(* Logix 5000 project; controller Test vendor 1 type 14 code 92 rev 33.11; software revision 33.00; part 2 of 2 *)

ADD_ON_INSTRUCTION Banner_CL50Pro_PD_v4   (* revision 4.0, vendor Banner Engineering *)
// Takes the raw SINT information and converts that data into actual information.
VAR_IN_OUT
   Process_Data : Banner_CL50Pro_PDO_v4; {required}
END_VAR
VAR_INPUT
   Byte_Swap : BOOL; {required}
END_VAR
VAR
   PDO_Temp : SINT[10]; {access None}
   PDI_Temp : SINT[2]; {access None}
END_VAR

ROUTINE Logic   (* ladder *)
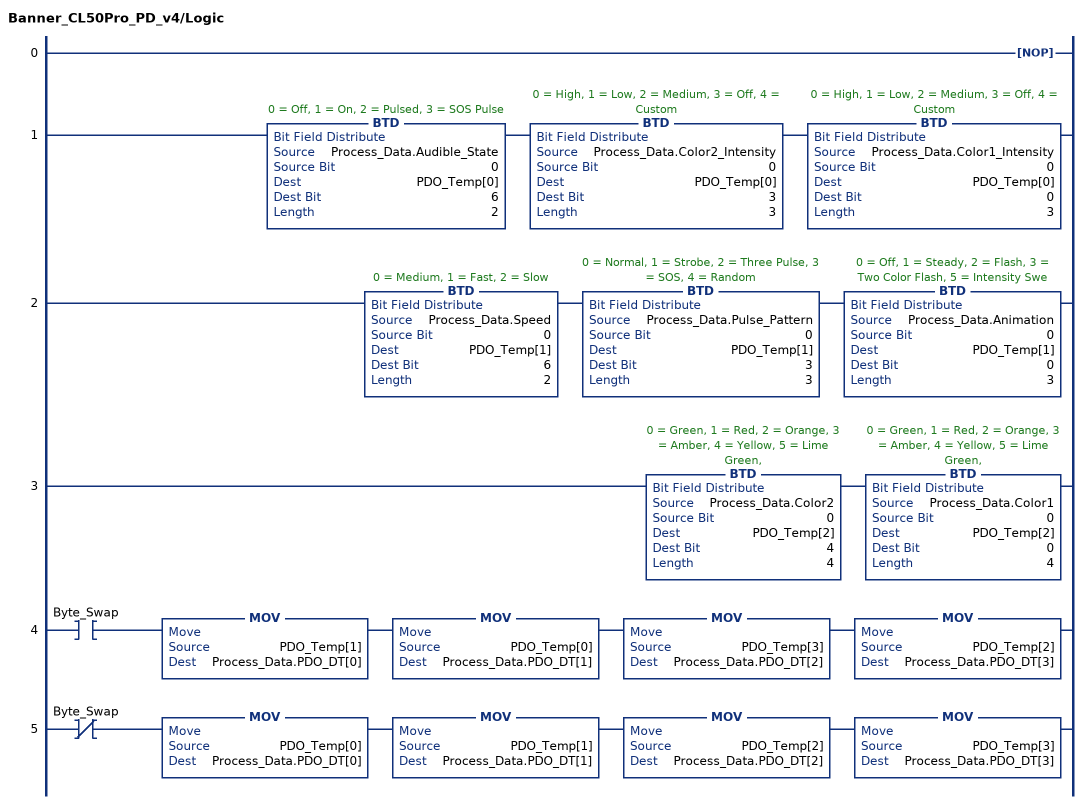
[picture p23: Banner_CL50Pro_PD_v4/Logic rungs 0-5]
   0: NOP();
   1: BTD(Process_Data.Audible_State,0,PDO_Temp[0],6,2)BTD(Process_Data.Color2_Intensity,0,PDO_Temp[0],3,3)BTD(Process_Data.Color1_Intensity,0,PDO_Temp[0],0,3);
   2: BTD(Process_Data.Speed,0,PDO_Temp[1],6,2)BTD(Process_Data.Pulse_Pattern,0,PDO_Temp[1],3,3)BTD(Process_Data.Animation,0,PDO_Temp[1],0,3);
   3: BTD(Process_Data.Color2,0,PDO_Temp[2],4,4)BTD(Process_Data.Color1,0,PDO_Temp[2],0,4);
   4: XIC(Byte_Swap)MOV(PDO_Temp[1],Process_Data.PDO_DT[0])MOV(PDO_Temp[0],Process_Data.PDO_DT[1])MOV(PDO_Temp[3],Process_Data.PDO_DT[2])MOV(PDO_Temp[2],Process_Data.PDO_DT[3]);
   5: XIO(Byte_Swap)MOV(PDO_Temp[0],Process_Data.PDO_DT[0])MOV(PDO_Temp[1],Process_Data.PDO_DT[1])MOV(PDO_Temp[2],Process_Data.PDO_DT[2])MOV(PDO_Temp[3],Process_Data.PDO_DT[3]);
END_ROUTINE
END_ADD_ON_INSTRUCTION

ADD_ON_INSTRUCTION Banner_DXMR90_IOLM_v4   (* revision 4.1, vendor Banner Engineering *)
// AOI that controls a Banner IO-Link Master with Banner devices.
// Revision note:
// Revised operational order for ISDU write.
VAR_IN_OUT
   IOLM : Banner_IOLM_v4; {required}
END_VAR
VAR
   Lock : DINT; {access None}
   Byte_Length : SINT; {access None}
   Current_Port : INT; {access None}   // Current port to communicate with via the IO-Link Master.
   Timer : TIMER := (PRE := 500); {access None}
   Error_Index : DINT; {access None}
   Timer2 : TIMER := (PRE := 5000); {access None}
   Temp_Index : INT; {access None}
   ErrCount : DINT; {access None}
   Timer4 : TIMER := (PRE := 2000); {access None}
   Timer5 : TIMER := (PRE := 2000); {access None}
   Timer3 : TIMER := (PRE := 2000); {access None}
   Timer6 : TIMER := (PRE := 3000); {access None}
   Timer7 : TIMER := (PRE := 3000); {access None}
END_VAR

ROUTINE Logic   (* ladder *)
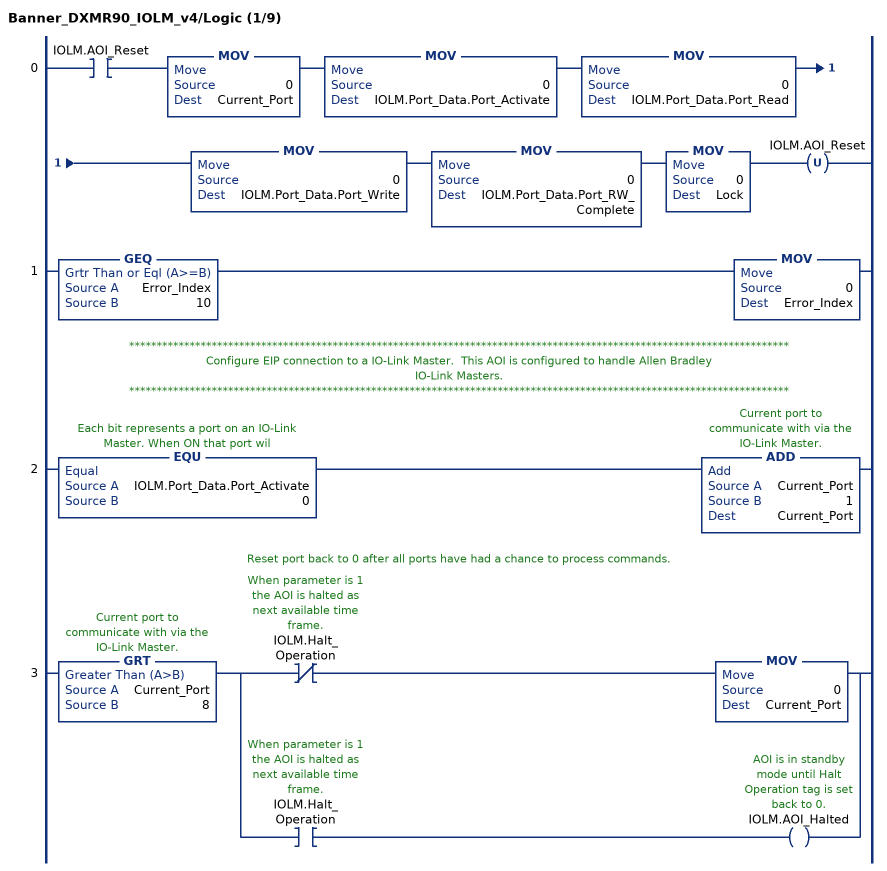
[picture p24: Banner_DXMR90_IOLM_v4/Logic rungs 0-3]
   0: XIC(IOLM.AOI_Reset)MOV(0,Current_Port)MOV(0,IOLM.Port_Data.Port_Activate)MOV(0,IOLM.Port_Data.Port_Read)MOV(0,IOLM.Port_Data.Port_Write)MOV(0,IOLM.Port_Data.Port_RW_Complete)MOV(0,Lock)OTU(IOLM.AOI_Reset);
   1: GEQ(Error_Index,10)MOV(0,Error_Index);
   // ************************************************************************************************************************
   // Configure EIP connection to a IO-Link Master.  This AOI is configured to handle Allen Bradley
   // IO-Link Masters.
   // ************************************************************************************************************************
   2: EQU(IOLM.Port_Data.Port_Activate,0)ADD(Current_Port,1,Current_Port);
   // Reset port back to 0 after all ports have had a chance to process commands.
   3: GRT(Current_Port,8)[XIO(IOLM.Halt_Operation) MOV(0,Current_Port) ,XIC(IOLM.Halt_Operation) OTE(IOLM.AOI_Halted) ];
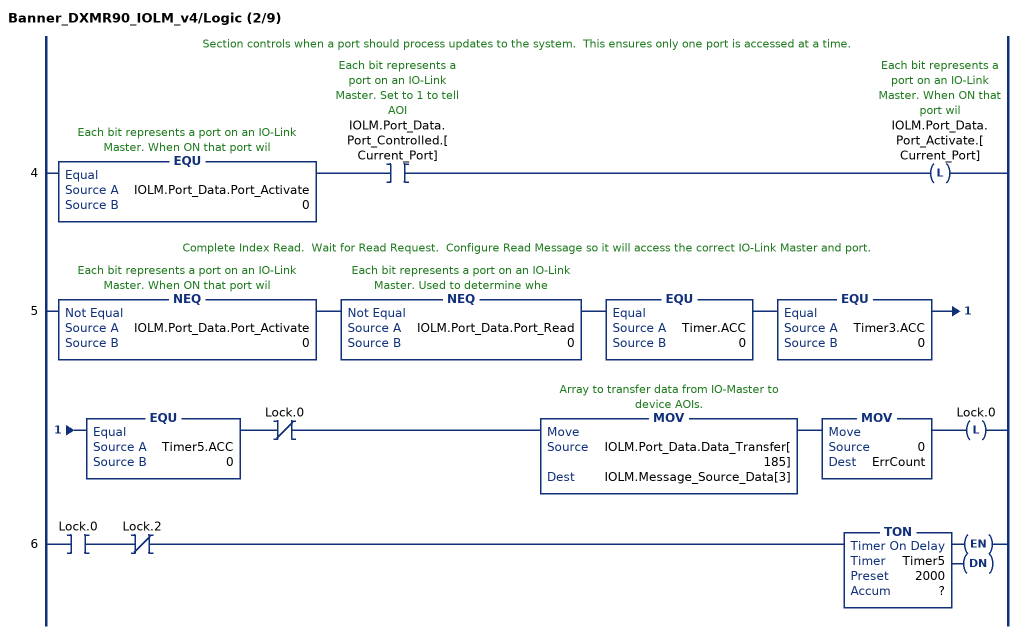
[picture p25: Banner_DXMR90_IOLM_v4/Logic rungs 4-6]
   // Section controls when a port should process updates to the system.  This ensures only one port is accessed at a time.
   4: EQU(IOLM.Port_Data.Port_Activate,0)XIC(IOLM.Port_Data.Port_Controlled.[Current_Port])OTL(IOLM.Port_Data.Port_Activate.[Current_Port]);
   // Complete Index Read.  Wait for Read Request.  Configure Read Message so it will access the correct IO-Link Master and port.
   5: NEQ(IOLM.Port_Data.Port_Activate,0)NEQ(IOLM.Port_Data.Port_Read,0)EQU(Timer.ACC,0)EQU(Timer3.ACC,0)EQU(Timer5.ACC,0)XIO(Lock.0)MOV(IOLM.Port_Data.Data_Transfer[185],IOLM.Message_Source_Data[3])MOV(0,ErrCount)OTL(Lock.0);
   6: XIC(Lock.0)XIO(Lock.2)TON(Timer5,?,?);
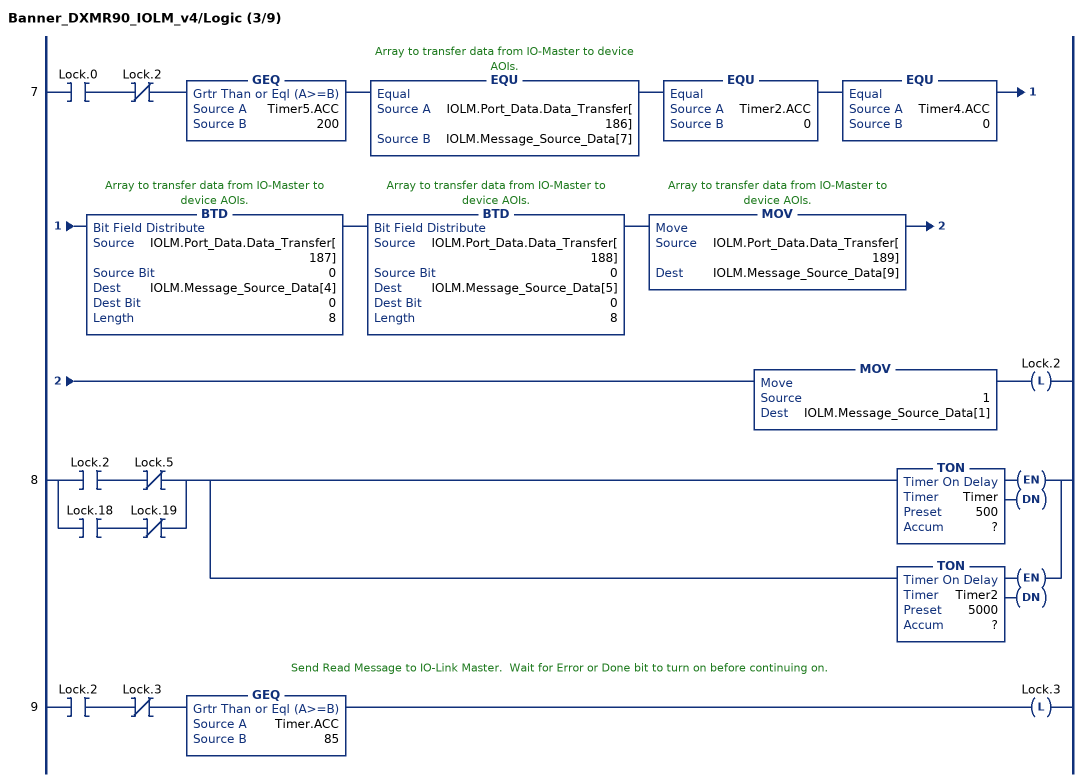
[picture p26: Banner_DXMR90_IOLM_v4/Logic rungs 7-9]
   7: XIC(Lock.0)XIO(Lock.2)GEQ(Timer5.ACC,200)EQU(IOLM.Port_Data.Data_Transfer[186],IOLM.Message_Source_Data[7])EQU(Timer2.ACC,0)EQU(Timer4.ACC,0)BTD(IOLM.Port_Data.Data_Transfer[187],0,IOLM.Message_Source_Data[4],0,8)BTD(IOLM.Port_Data.Data_Transfer[188],0,IOLM.Message_Source_Data[5],0,8)MOV(IOLM.Port_Data.Data_Transfer[189],IOLM.Message_Source_Data[9])MOV(1,IOLM.Message_Source_Data[1])OTL(Lock.2);
   8: [XIC(Lock.2) XIO(Lock.5) ,XIC(Lock.18) XIO(Lock.19) ][TON(Timer,?,?) ,TON(Timer2,?,?) ];
   // Send Read Message to IO-Link Master.  Wait for Error or Done bit to turn on before continuing on.
   9: XIC(Lock.2)XIO(Lock.3)GEQ(Timer.ACC,85)OTL(Lock.3);
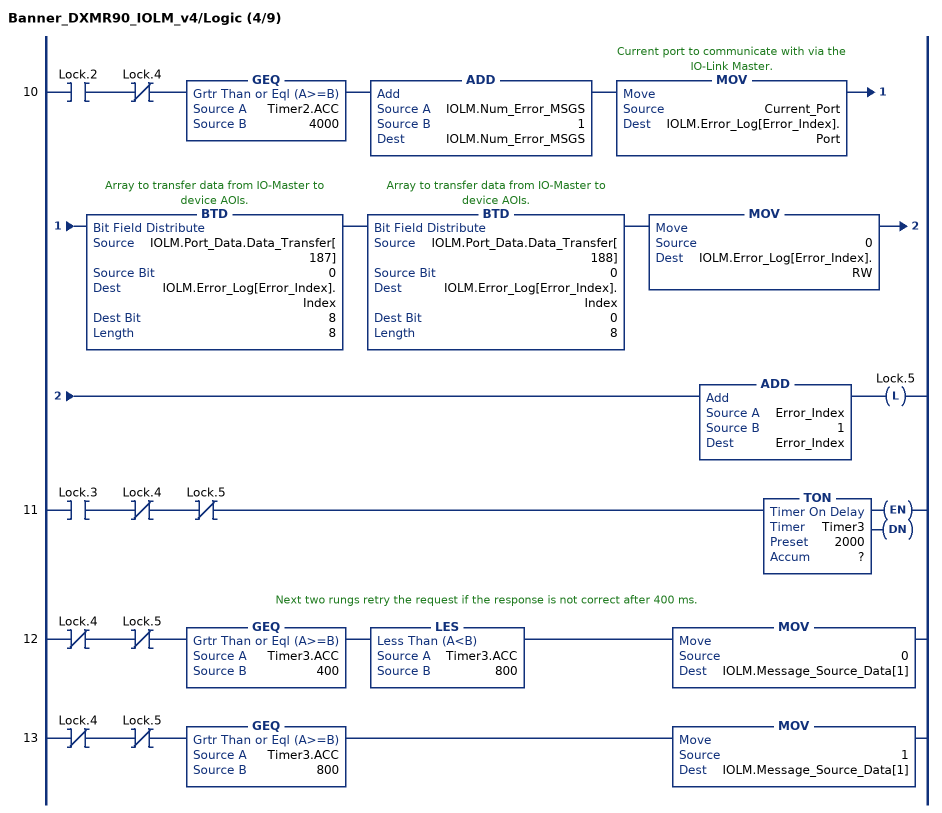
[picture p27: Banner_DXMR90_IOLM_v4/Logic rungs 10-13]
   10: XIC(Lock.2)XIO(Lock.4)GEQ(Timer2.ACC,4000)ADD(IOLM.Num_Error_MSGS,1,IOLM.Num_Error_MSGS)MOV(Current_Port,IOLM.Error_Log[Error_Index].Port)BTD(IOLM.Port_Data.Data_Transfer[187],0,IOLM.Error_Log[Error_Index].Index,8,8)BTD(IOLM.Port_Data.Data_Transfer[188],0,IOLM.Error_Log[Error_Index].Index,0,8)MOV(0,IOLM.Error_Log[Error_Index].RW)ADD(Error_Index,1,Error_Index)OTL(Lock.5);
   11: XIC(Lock.3)XIO(Lock.4)XIO(Lock.5)TON(Timer3,?,?);
   // Next two rungs retry the request if the response is not correct after 400 ms.
   12: XIO(Lock.4)XIO(Lock.5)GEQ(Timer3.ACC,400)LES(Timer3.ACC,800)MOV(0,IOLM.Message_Source_Data[1]);
   13: XIO(Lock.4)XIO(Lock.5)GEQ(Timer3.ACC,800)MOV(1,IOLM.Message_Source_Data[1]);
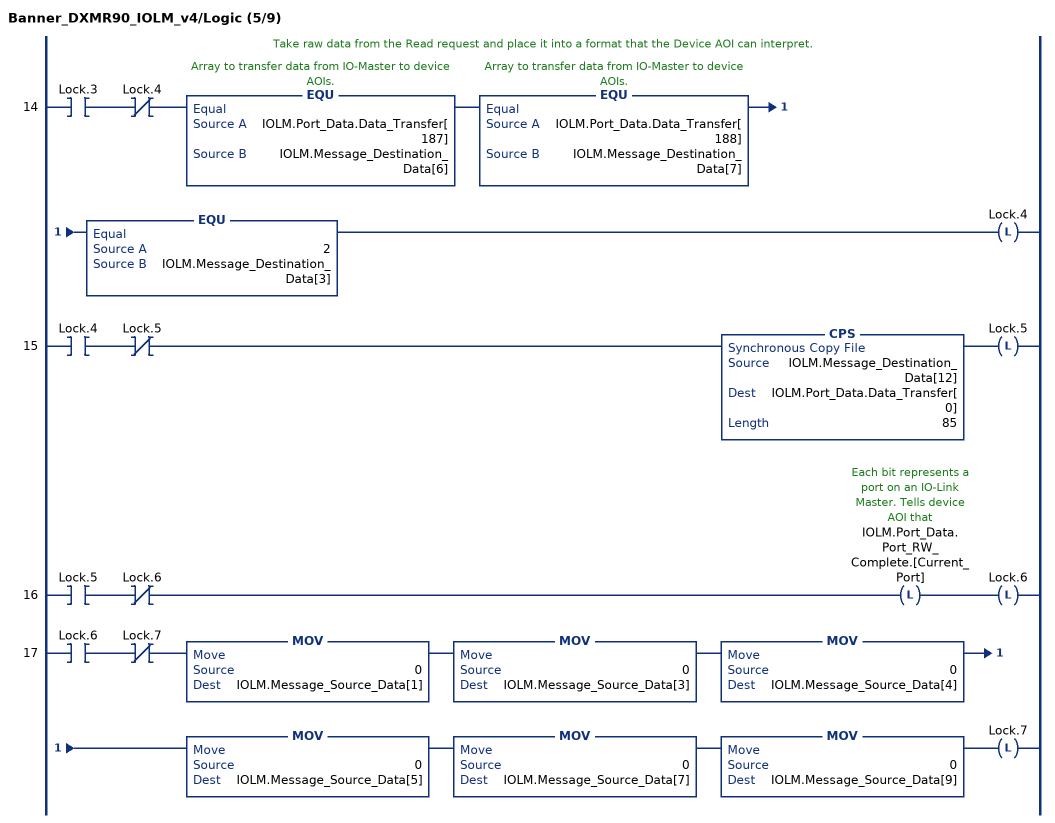
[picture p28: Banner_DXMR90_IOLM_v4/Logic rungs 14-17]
   // Take raw data from the Read request and place it into a format that the Device AOI can interpret.
   14: XIC(Lock.3)XIO(Lock.4)EQU(IOLM.Port_Data.Data_Transfer[187],IOLM.Message_Destination_Data[6])EQU(IOLM.Port_Data.Data_Transfer[188],IOLM.Message_Destination_Data[7])EQU(2,IOLM.Message_Destination_Data[3])OTL(Lock.4);
   15: XIC(Lock.4)XIO(Lock.5)CPS(IOLM.Message_Destination_Data[12],IOLM.Port_Data.Data_Transfer[0],85)OTL(Lock.5);
   16: XIC(Lock.5)XIO(Lock.6)OTL(IOLM.Port_Data.Port_RW_Complete.[Current_Port])OTL(Lock.6);
   17: XIC(Lock.6)XIO(Lock.7)MOV(0,IOLM.Message_Source_Data[1])MOV(0,IOLM.Message_Source_Data[3])MOV(0,IOLM.Message_Source_Data[4])MOV(0,IOLM.Message_Source_Data[5])MOV(0,IOLM.Message_Source_Data[7])MOV(0,IOLM.Message_Source_Data[9])OTL(Lock.7);
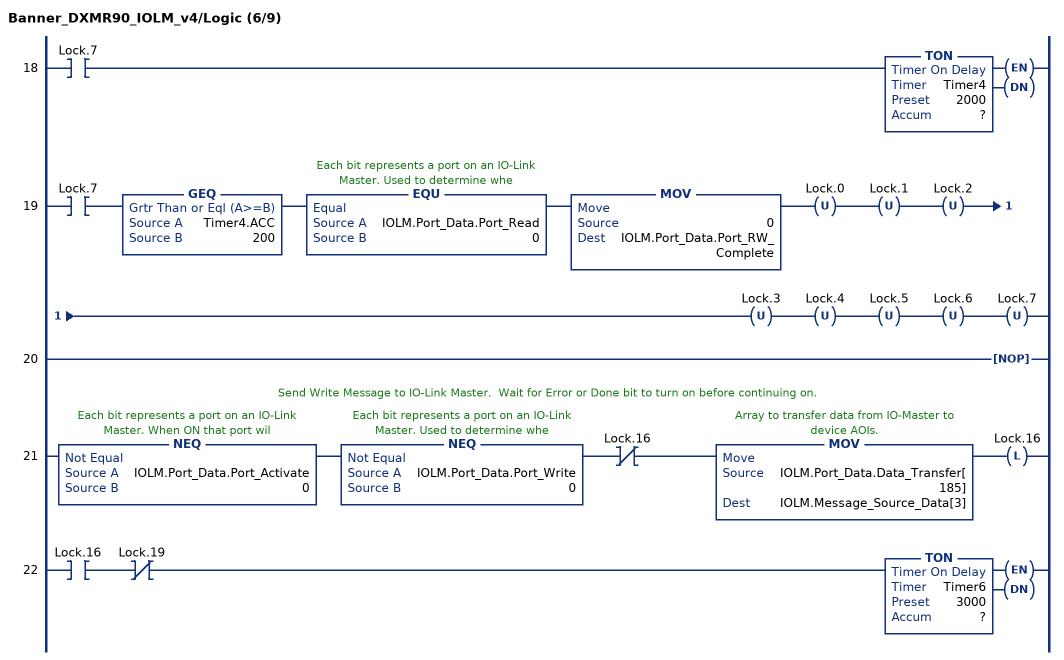
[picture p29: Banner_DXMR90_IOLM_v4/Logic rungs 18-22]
   18: XIC(Lock.7)TON(Timer4,?,?);
   19: XIC(Lock.7)GEQ(Timer4.ACC,200)EQU(IOLM.Port_Data.Port_Read,0)MOV(0,IOLM.Port_Data.Port_RW_Complete)OTU(Lock.0)OTU(Lock.1)OTU(Lock.2)OTU(Lock.3)OTU(Lock.4)OTU(Lock.5)OTU(Lock.6)OTU(Lock.7);
   20: NOP();
   // Send Write Message to IO-Link Master.  Wait for Error or Done bit to turn on before continuing on.
   21: NEQ(IOLM.Port_Data.Port_Activate,0)NEQ(IOLM.Port_Data.Port_Write,0)XIO(Lock.16)MOV(IOLM.Port_Data.Data_Transfer[185],IOLM.Message_Source_Data[3])OTL(Lock.16);
   22: XIC(Lock.16)XIO(Lock.19)TON(Timer6,?,?);
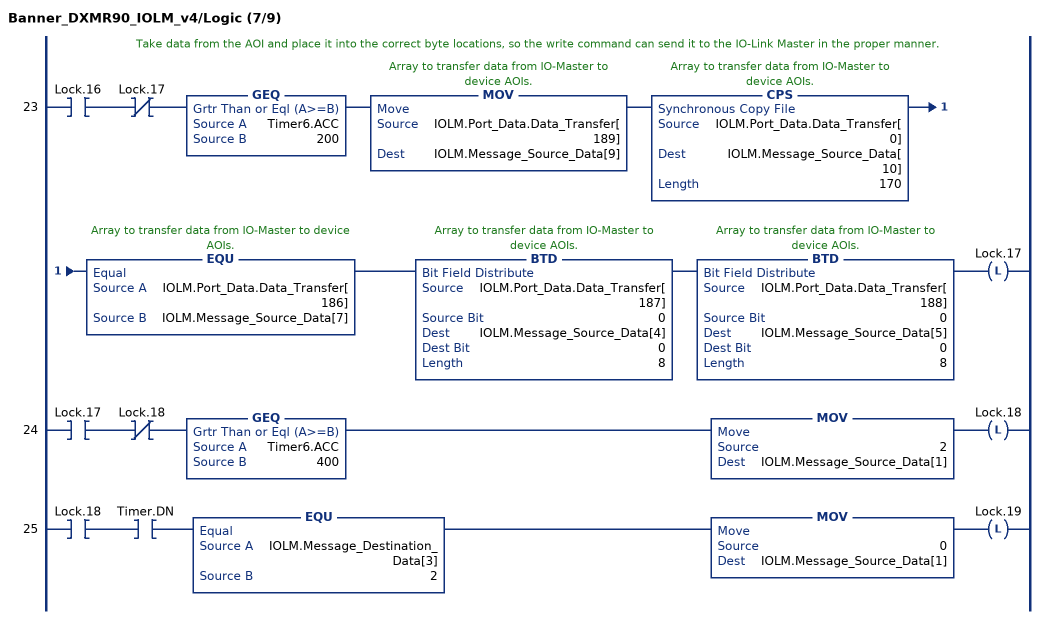
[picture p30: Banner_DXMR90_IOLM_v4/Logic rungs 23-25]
   // Take data from the AOI and place it into the correct byte locations, so the write command can send it to the IO-Link Master in the proper manner.
   23: XIC(Lock.16)XIO(Lock.17)GEQ(Timer6.ACC,200)MOV(IOLM.Port_Data.Data_Transfer[189],IOLM.Message_Source_Data[9])CPS(IOLM.Port_Data.Data_Transfer[0],IOLM.Message_Source_Data[10],170)EQU(IOLM.Port_Data.Data_Transfer[186],IOLM.Message_Source_Data[7])BTD(IOLM.Port_Data.Data_Transfer[187],0,IOLM.Message_Source_Data[4],0,8)BTD(IOLM.Port_Data.Data_Transfer[188],0,IOLM.Message_Source_Data[5],0,8)OTL(Lock.17);
   24: XIC(Lock.17)XIO(Lock.18)GEQ(Timer6.ACC,400)MOV(2,IOLM.Message_Source_Data[1])OTL(Lock.18);
   25: XIC(Lock.18)XIC(Timer.DN)EQU(IOLM.Message_Destination_Data[3],2)MOV(0,IOLM.Message_Source_Data[1])OTL(Lock.19);
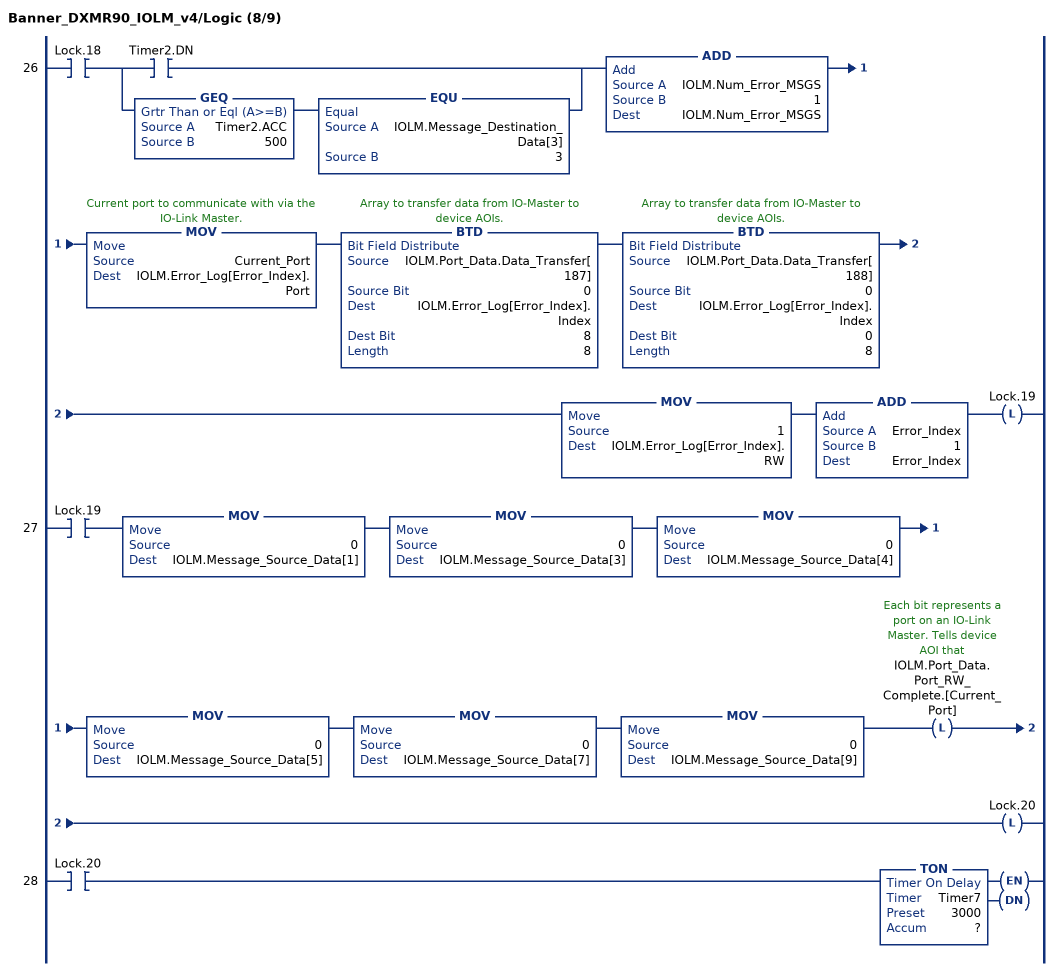
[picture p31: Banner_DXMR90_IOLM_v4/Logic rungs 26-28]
   26: XIC(Lock.18)[XIC(Timer2.DN) ,GEQ(Timer2.ACC,500) EQU(IOLM.Message_Destination_Data[3],3) ]ADD(IOLM.Num_Error_MSGS,1,IOLM.Num_Error_MSGS)MOV(Current_Port,IOLM.Error_Log[Error_Index].Port)BTD(IOLM.Port_Data.Data_Transfer[187],0,IOLM.Error_Log[Error_Index].Index,8,8)BTD(IOLM.Port_Data.Data_Transfer[188],0,IOLM.Error_Log[Error_Index].Index,0,8)MOV(1,IOLM.Error_Log[Error_Index].RW)ADD(Error_Index,1,Error_Index)OTL(Lock.19);
   27: XIC(Lock.19)MOV(0,IOLM.Message_Source_Data[1])MOV(0,IOLM.Message_Source_Data[3])MOV(0,IOLM.Message_Source_Data[4])MOV(0,IOLM.Message_Source_Data[5])MOV(0,IOLM.Message_Source_Data[7])MOV(0,IOLM.Message_Source_Data[9])OTL(IOLM.Port_Data.Port_RW_Complete.[Current_Port])OTL(Lock.20);
   28: XIC(Lock.20)TON(Timer7,?,?);
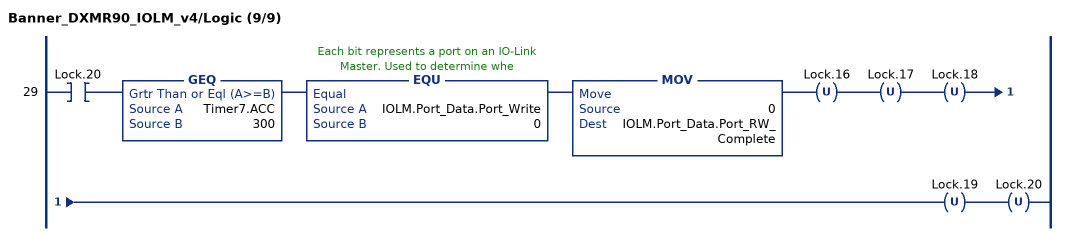
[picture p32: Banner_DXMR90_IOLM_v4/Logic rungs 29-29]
   29: XIC(Lock.20)GEQ(Timer7.ACC,300)EQU(IOLM.Port_Data.Port_Write,0)MOV(0,IOLM.Port_Data.Port_RW_Complete)OTU(Lock.16)OTU(Lock.17)OTU(Lock.18)OTU(Lock.19)OTU(Lock.20);
END_ROUTINE
END_ADD_ON_INSTRUCTION

VAR_GLOBAL   (* controller tags *)
   CL50_IOLM1_01 : Banner_CL50Pro_v4 := (Initial_Global_Read := 1);
   CL50_IOLM1_01_PD : Banner_CL50Pro_PDO_v4;
   CL50_IOLM1_01_PD_Status : Banner_CL50Pro_PD_v4;
   CL50_IOLM1_01_Status : Banner_CL50Pro_Param_v4;
   IOLM1 : Banner_IOLM_v4;
   IOLM1_Status : Banner_DXMR90_IOLM_v4;
   Manual_Reset : BOOL;
END_VAR

PROGRAM MainProgram   (* main routine MainRoutine *)

ROUTINE MainRoutine   (* ladder *)
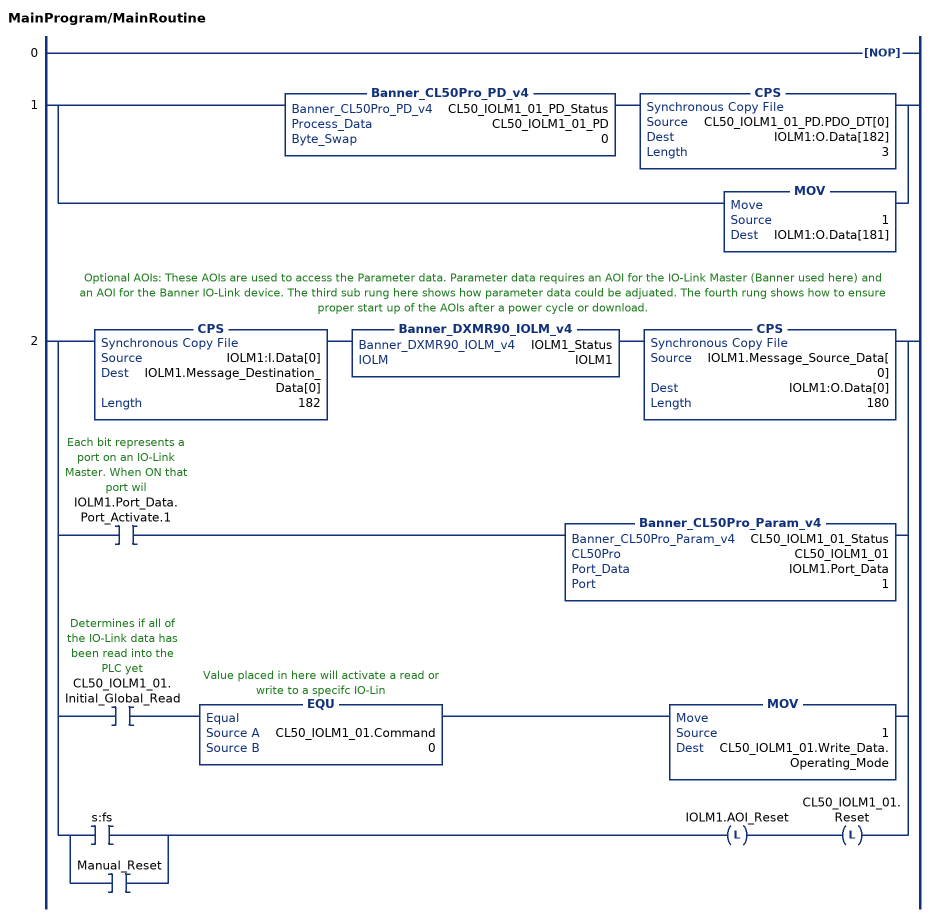
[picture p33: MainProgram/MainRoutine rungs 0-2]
   0: NOP();
   1: [Banner_CL50Pro_PD_v4(CL50_IOLM1_01_PD_Status,CL50_IOLM1_01_PD,0) CPS(CL50_IOLM1_01_PD.PDO_DT[0],IOLM1:O.Data[182],3) ,MOV(1,IOLM1:O.Data[181]) ];
   // Optional AOIs: These AOIs are used to access the Parameter data. Parameter data requires an AOI for the IO-Link Master (Banner used here) and an AOI for the Banner IO-Link device. The third sub rung here shows how parameter data could be adjuated. The fourth rung shows how to ensure proper start up of the AOIs after a power cycle or download.
   2: [CPS(IOLM1:I.Data[0],IOLM1.Message_Destination_Data[0],182) Banner_DXMR90_IOLM_v4(IOLM1_Status,IOLM1) CPS(IOLM1.Message_Source_Data[0],IOLM1:O.Data[0],180) ,XIC(IOLM1.Port_Data.Port_Activate.1) Banner_CL50Pro_Param_v4(CL50_IOLM1_01_Status,CL50_IOLM1_01,IOLM1.Port_Data,1) ,XIC(CL50_IOLM1_01.Initial_Global_Read) EQU(CL50_IOLM1_01.Command,0) MOV(1,CL50_IOLM1_01.Write_Data.Operating_Mode) ,[XIC(s:fs) ,XIC(Manual_Reset) ] OTL(IOLM1.AOI_Reset) OTL(CL50_IOLM1_01.Reset) ];
END_ROUTINE
END_PROGRAM
